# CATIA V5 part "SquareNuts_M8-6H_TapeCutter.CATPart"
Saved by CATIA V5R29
Part number: SquareNuts_M8-6H_TapeCutter
Bounding box of the stored display mesh (mm): x -7 to 7, y -7 to 7, z -3 to 3
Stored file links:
  C:\Users\Administrator\Desktop\프로젝트\Boxfold\TapeCutter\SqaureNuts_M8-6H.CATPart
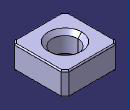
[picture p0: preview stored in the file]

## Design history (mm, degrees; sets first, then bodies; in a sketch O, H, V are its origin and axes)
Body1 (main body)
  Sketch1 on xy-plane, origin (0, 0, 0), H (1, 0, 0), V (0, 1, 0)
    line L1 (7, 7) -> (7, -7)
    line L2 (7, -7) -> (-7, -7)
    line L3 (-7, -7) -> (-7, 7)
    line L4 (-7, 7) -> (7, 7)
    length L3 = 14
    length L4 = 14
    vertical: L1 V, L3 V
    horizontal: L2 H, L4 H
    equidistance: L1 L3 O, L2 L4 O
  Pad1: profile Sketch1, direction (0, 0, 1), length 3, mirrored extent
  Sketch2 on end face of Pad1, origin (0.3753, 1.5089, 3), H (1, 0, 0), V (0, 1, 0)
    point P1 (-0.3753, -1.5089)
    reference projected line E1 (6.6247, -8.5089) -> (6.6247, 5.4911) from edge [face of Pad1 from Sketch1.L1 | end face of Pad1]
    reference projected line E2 (6.6247, 5.4911) -> (-7.3753, 5.4911) from edge [face of Pad1 from Sketch1.L4 | end face of Pad1]
    distance P1 E1 = 7
    distance E2 P1 = 7
  Hole1: placed by Sketch2, at (0, 0, 3) direction (0, 0, -1), diameter 6.647, through (limit type 3), threaded "M8", thread diameter 8, thread depth 6, pitch 1.25
  Chamfer1: length 1, angle 45, on face of Hole1; edge [face of Pad1 from Sketch1.L4 | face of Pad1 from Sketch1.L1]; edge [face of Pad1 from Sketch1.L3 | face of Pad1 from Sketch1.L4]; edge [face of Pad1 from Sketch1.L1 | face of Pad1 from Sketch1.L2]; edge [face of Pad1 from Sketch1.L2 | face of Pad1 from Sketch1.L3]
  Fillet1: radius 0.3, on edge [face of Pad1 from Sketch1.L3 | end face of Pad1]; edge [end face of Pad1 | face of Chamfer1] (x4); edge [face of Pad1 from Sketch1.L2 | end face of Pad1]; edge [face of Pad1 from Sketch1.L1 | end face of Pad1]; edge [face of Pad1 from Sketch1.L4 | end face of Pad1]; edge [start face of Pad1 | face of Pad1 from Sketch1.L3]; edge [start face of Pad1 | face of Chamfer1] (x4); edge [start face of Pad1 | face of Pad1 from Sketch1.L2]; edge [start face of Pad1 | face of Pad1 from Sketch1.L1]; edge [start face of Pad1 | face of Pad1 from Sketch1.L4]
